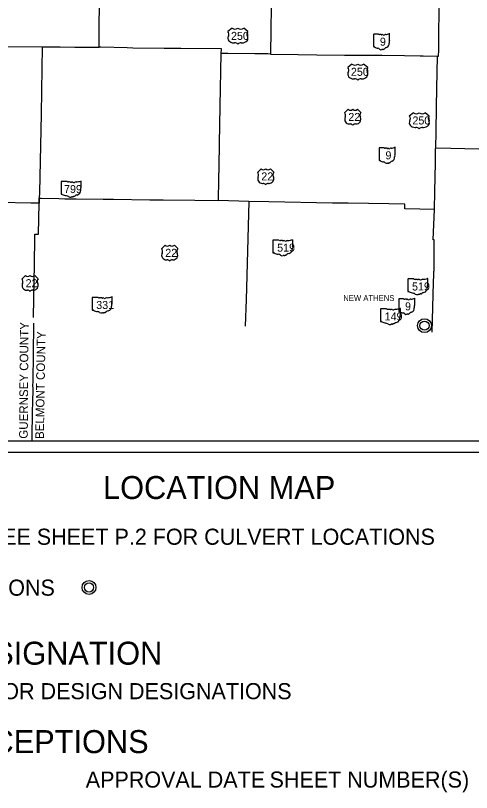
# Model space of a CAD drawing. Extents: x 0 to 34, y -32.5 to 22.
# Drawn here: x 3.67 to 7.63, y 11.04 to 17.8 of the extents above; entities that cross this region are included whole.
import ezdxf

# ---------------------------------------------------------------- set-up
doc = ezdxf.new("R2010")
doc.units = 0
for name, color, linetype in [('GM_X_Adjacent_County', 7, 'Continuous'), ('GM_X_County_Road', 7, 'Continuous'), ('GM_X_County_Road_Text', 7, 'Continuous'), ('GM_X_County_ROW', 7, 'Continuous'), ('GM_X_Minor_Lake_Text', 7, 'Continuous'), ('GM_X_Minor_River', 7, 'Continuous'), ('GM_X_Minor_River_Text', 7, 'Continuous'), ('GM_X_Township', 7, 'Continuous')]:
    doc.layers.add(name, color=color, linetype=linetype)

msp = doc.modelspace()

# ---------------------------------------------------------------- linework, layer by layer
at = {"layer": 'GM_X_Adjacent_County'}
for centre, radius in [((7.2238, 15.1013), 0.06), ((7.2238, 15.1013), 0.04), ((4.3048, 12.8249), 0.06), ((4.3048, 12.8249), 0.04)]:
    msp.add_circle(centre, radius, dxfattribs=at)
at = {"layer": 'GM_X_County_Road_Text'}
msp.add_lwpolyline([(3.8222, 15.1223), (3.819, 14.8503), (3.8155, 14.6249), (3.8154, 14.617), (3.8142, 14.5801), (3.8147, 14.554), (3.8122, 14.4309), (3.8104, 14.3615), (3.8091, 14.3107), (3.8066, 14.1687), (3.8059, 14.1)], dxfattribs=at)
at = {"layer": 'GM_X_County_ROW'}
for points in [[(7.321, 16.6465), (7.3246, 16.7856), (7.3288, 17.0035), (7.3306, 17.1648), (7.3383, 17.4444), (7.3468, 17.4448), (7.3472, 17.4976), (7.3491, 17.6075), (7.3489, 17.6422), (7.3523, 17.8326), (7.3534, 17.8901), (7.3544, 17.9622), (7.3569, 18.1501), (7.3595, 18.2961), (7.3593, 18.3312), (7.3616, 18.5062), (7.3799, 18.5062), (7.6271, 18.5029), (7.8521, 18.4984), (8.053, 18.4945), (8.318, 18.489), (8.6937, 18.4776)], [(5.8906, 17.8717), (5.8866, 17.6728), (5.8829, 17.4634), (5.8599, 17.4636), (5.8264, 17.464), (5.749, 17.4649), (5.5121, 17.4676), (5.4556, 17.4683), (5.4565, 17.5071), (5.1048, 17.5102), (4.9592, 17.5125), (4.6867, 17.5154), (4.6367, 17.5168), (4.4077, 17.5228), (4.393, 17.5229), (4.3934, 17.5648), (4.3922, 17.686), (4.3981, 18.1308)], [(3.0949, 17.5354), (3.2293, 17.5323), (3.8985, 17.5258), (3.8919, 17.1439), (3.8881, 16.941), (3.8731, 16.2596), (3.8722, 16.2095), (3.8718, 16.1665), (3.7972, 16.1673), (3.5262, 16.1718), (3.5138, 16.1719), (3.2094, 16.176), (2.6123, 16.1865), (2.2906, 16.1847), (2.2448, 16.1852)], [(3.8985, 17.5258), (3.9008, 17.5257), (4.0551, 17.525), (4.1816, 17.524), (4.393, 17.5229)], [(7.3099, 16.1125), (7.056, 16.1178), (7.0526, 16.1179), (7.0541, 16.158), (6.9134, 16.1606), (6.5592, 16.1659), (6.4234, 16.1677), (5.8693, 16.1781), (5.6952, 16.1822), (5.4311, 16.189), (5.4351, 16.3752), (5.4369, 16.4875), (5.44, 16.6831), (5.4471, 17.0112), (5.4556, 17.4683)], [(5.8829, 17.4634), (6.1235, 17.4606), (6.2881, 17.4575), (6.5279, 17.4525), (6.8541, 17.4535), (7.0492, 17.4506), (7.1868, 17.4473), (7.2109, 17.4467), (7.3383, 17.4444)], [(7.2893, 15.0436), (7.3033, 15.4758), (7.3037, 15.5438), (7.3048, 15.5766), (7.3083, 15.5766), (7.3085, 15.7229), (7.3089, 15.8468), (7.2997, 15.8466), (7.3099, 16.1125), (7.3135, 16.2676), (7.3192, 16.5173), (7.3208, 16.6424), (7.321, 16.6465), (7.4531, 16.644), (7.8197, 16.6369), (8.1172, 16.6295), (8.1959, 16.6272), (8.2442, 16.6261), (8.3923, 16.6228), (8.6528, 16.6128)], [(3.8226, 15.171), (3.828, 15.5021), (3.8281, 15.5137), (3.8294, 15.6038), (3.8339, 15.8975), (3.8649, 15.897), (3.8718, 16.1665), (3.8722, 16.2095), (3.8872, 16.2094), (4.0414, 16.2069), (4.0954, 16.2051), (4.1927, 16.2039), (4.4267, 16.2022), (4.5177, 16.2007), (4.8334, 16.1961), (4.9511, 16.1945), (5.2258, 16.1916), (5.4311, 16.189)], [(5.6952, 16.1822), (5.6755, 15.4296), (5.6732, 15.3285), (5.6632, 15.0971)]]:
    msp.add_lwpolyline(points, dxfattribs=at)
at = {"layer": 'GM_X_Minor_Lake_Text'}
for p, q in [((5.5495, 17.6879), (5.5132, 17.6589)), ((5.6872, 17.6589), (5.651, 17.6879)), ((5.564, 17.5602), (5.5712, 17.5602)), ((5.6292, 17.5602), (5.6365, 17.5602)), ((6.5927, 17.3755), (6.5565, 17.3465)), ((6.7305, 17.3465), (6.6942, 17.3755)), ((6.6072, 17.2478), (6.6145, 17.2478)), ((6.6725, 17.2478), (6.6797, 17.2478)), ((6.559, 16.9828), (6.53, 16.9538)), ((6.6692, 16.9538), (6.6402, 16.9828)), ((7.128, 16.9524), (7.0917, 16.9234)), ((7.2657, 16.9234), (7.2295, 16.9524)), ((6.5706, 16.8552), (6.5764, 16.8552)), ((6.6228, 16.8552), (6.6286, 16.8552)), ((7.1425, 16.8248), (7.1497, 16.8248)), ((7.2077, 16.8248), (7.215, 16.8248)), ((5.8017, 16.466), (5.7727, 16.437)), ((5.9119, 16.437), (5.8829, 16.466)), ((5.8133, 16.3384), (5.8191, 16.3384)), ((5.8655, 16.3384), (5.8713, 16.3384)), ((4.9662, 15.8012), (4.9372, 15.7722)), ((5.0764, 15.7722), (5.0474, 15.8012)), ((4.9778, 15.6736), (4.9836, 15.6736)), ((5.03, 15.6736), (5.0358, 15.6736)), ((3.7513, 15.5374), (3.7223, 15.5084)), ((3.8615, 15.5084), (3.8325, 15.5374)), ((3.7629, 15.4098), (3.7687, 15.4098)), ((3.8151, 15.4098), (3.8209, 15.4098))]:
    msp.add_line(p, q, dxfattribs=at)
for centre, radius, start, end in [((6.5793, 17.0035), 0.029, 225.573, 314.427), ((6.6199, 17.0035), 0.029, 225.573, 314.427), ((6.5701, 16.8958), 0.0406, 154.83192, 270.63826), ((6.4967, 16.9305), 0.0406, 334.54712, 35.00093), ((6.629, 16.8958), 0.0406, 269.36174, 25.16808), ((6.7024, 16.9305), 0.0406, 144.99907, 205.45288), ((6.5764, 16.8262), 0.029, 36.8699, 90), ((6.6228, 16.8262), 0.029, 90, 143.1301), ((5.7394, 16.4137), 0.0406, 334.54712, 35.00093), ((5.822, 16.4867), 0.029, 225.573, 314.427), ((5.8626, 16.4867), 0.029, 225.573, 314.427), ((5.9452, 16.4137), 0.0406, 144.99907, 205.45288), ((5.8129, 16.379), 0.0406, 154.83192, 270.63826), ((5.8718, 16.379), 0.0406, 269.36174, 25.16808), ((5.8191, 16.3094), 0.029, 36.8699, 90), ((5.8655, 16.3094), 0.029, 90, 143.1301), ((4.9039, 15.7489), 0.0406, 334.54712, 35.00093), ((4.9865, 15.8219), 0.029, 225.573, 314.427), ((5.0271, 15.8219), 0.029, 225.573, 314.427), ((5.1096, 15.7489), 0.0406, 144.99907, 205.45288), ((4.9773, 15.7142), 0.0406, 154.83192, 270.63826), ((5.0362, 15.7142), 0.0406, 269.36174, 25.16808), ((4.9836, 15.6446), 0.029, 36.8699, 90), ((5.03, 15.6446), 0.029, 90, 143.1301), ((3.6891, 15.4851), 0.0406, 334.54712, 35.00093), ((3.7716, 15.5581), 0.029, 225.573, 314.427), ((3.8122, 15.5581), 0.029, 225.573, 314.427), ((3.8948, 15.4851), 0.0406, 144.99907, 205.45288), ((3.7625, 15.4504), 0.0406, 154.83192, 270.63826), ((3.7687, 15.3808), 0.029, 36.8699, 90), ((3.8151, 15.3808), 0.029, 90, 143.1301), ((3.8214, 15.4504), 0.0406, 269.36174, 25.16808)]:
    msp.add_arc(centre, radius, start, end, dxfattribs=at)
for centre, major_axis, start_param, end_param in [((5.4716, 17.6356), (0.0508, 0), 5.838949, 6.894067), ((5.5749, 17.7086), (-0.0363, 0), 0.795399, 2.346194), ((5.6256, 17.7086), (-0.0363, 0), 0.795399, 2.346194), ((5.7288, 17.6356), (-0.0508, 0), 5.672304, 6.727422), ((5.5634, 17.6008), (0.0508, 0), 2.702327, 4.723529), ((5.6371, 17.6008), (-0.0508, 0), 1.559657, 3.580859), ((5.5712, 17.5312), (-0.0363, 0), 3.785094, 4.712389), ((5.6292, 17.5312), (-0.0363, 0), 4.712389, 5.639684), ((6.6181, 17.3962), (-0.0363, 0), 0.795399, 2.346194), ((6.6688, 17.3962), (-0.0363, 0), 0.795399, 2.346194), ((6.6066, 17.2884), (0.0508, 0), 2.702327, 4.723529), ((6.5149, 17.3232), (0.0508, 0), 5.838949, 6.894067), ((6.6803, 17.2884), (-0.0508, 0), 1.559657, 3.580859), ((6.7721, 17.3232), (-0.0508, 0), 5.672304, 6.727422), ((6.6145, 17.2188), (-0.0363, 0), 3.785094, 4.712389), ((6.6725, 17.2188), (-0.0363, 0), 4.712389, 5.639684), ((7.0501, 16.9001), (0.0508, 0), 5.838949, 6.894067), ((7.1534, 16.9731), (-0.0363, 0), 0.795399, 2.346194), ((7.2041, 16.9731), (-0.0363, 0), 0.795399, 2.346194), ((7.3073, 16.9001), (-0.0508, 0), 5.672304, 6.727422), ((7.1419, 16.8654), (0.0508, 0), 2.702327, 4.723529), ((7.1497, 16.7958), (-0.0363, 0), 3.785094, 4.712389), ((7.2077, 16.7958), (-0.0363, 0), 4.712389, 5.639684), ((7.2155, 16.8654), (-0.0508, 0), 1.559657, 3.580859)]:
    msp.add_ellipse(centre, major_axis=major_axis, ratio=0.8, start_param=start_param, end_param=end_param, dxfattribs=at)
at = {"layer": 'GM_X_Minor_River_Text'}
for p, q in [((6.7815, 17.6342), (6.7815, 17.5285)), ((6.8236, 17.636), (6.7829, 17.636)), ((6.9207, 17.5834), (6.9207, 17.6386)), ((6.9207, 17.5834), (6.9207, 17.5834)), ((6.8297, 16.646), (6.8297, 16.5403)), ((6.8718, 16.6478), (6.831, 16.6478)), ((6.9689, 16.5951), (6.9689, 16.6504)), ((6.9689, 16.5951), (6.9689, 16.5951)), ((4.0616, 16.3525), (4.0616, 16.2468)), ((4.1142, 16.3543), (4.0633, 16.3543)), ((4.2356, 16.3016), (4.2356, 16.3569)), ((4.2356, 16.3017), (4.2356, 16.3016)), ((5.9051, 15.8427), (5.9051, 15.7371)), ((5.9578, 15.8446), (5.9069, 15.8446)), ((6.0792, 15.7919), (6.0792, 15.8472)), ((6.0791, 15.7919), (6.0792, 15.7919)), ((7.0786, 15.5053), (7.0786, 15.3996)), ((7.1313, 15.5071), (7.0803, 15.5071)), ((7.2526, 15.4544), (7.2526, 15.5097)), ((7.2526, 15.4544), (7.2526, 15.4544)), ((4.3321, 15.3447), (4.3321, 15.239)), ((4.3848, 15.3465), (4.3339, 15.3465)), ((4.5062, 15.2938), (4.5062, 15.3491)), ((7.1394, 15.2819), (7.1394, 15.3372)), ((4.5062, 15.2938), (4.5062, 15.2938)), ((7.0002, 15.3328), (7.0002, 15.2271)), ((7.0423, 15.3346), (7.0015, 15.3346)), ((7.1394, 15.282), (7.1394, 15.2819)), ((6.8408, 15.2446), (6.8408, 15.1389)), ((6.8935, 15.2464), (6.8425, 15.2464)), ((7.0148, 15.1937), (7.0148, 15.249)), ((7.0148, 15.1937), (7.0148, 15.1937))]:
    msp.add_line(p, q, dxfattribs=at)
for centre, radius, start, end in [((6.7831, 17.6344), 0.00161, 98.1301, 188.1301), ((6.8333, 17.6483), 0.0156, 231.61951, 271.11188), ((6.8385, 17.5767), 0.0562, 80.48669, 94.98827), ((6.8899, 17.6037), 0.0297, 97.34618, 120.76885), ((6.8711, 17.7801), 0.1476, 275.84447, 288.90645), ((6.9192, 17.6389), 0.00155, 351.86209, 97.738), ((6.8513, 17.635), 0.00451, 219.79206, 297.10237), ((6.8579, 17.6228), 0.00938, 54.46668, 119.14113), ((6.87, 17.6395), 0.0113, 233.85621, 294.82819), ((6.9262, 17.5602), 0.0105, 136.8065, 186.92959), ((6.9203, 17.5793), 0.0024, 107.94398, 210.33697), ((6.9051, 17.5723), 0.0144, 340.03296, 23.64957), ((6.919, 17.5831), 0.00166, 289.60381, 7.73413), ((6.7831, 17.5283), 0.00163, 171.95839, 258.30661), ((6.7833, 17.5391), 0.0124, 267.33899, 280.60386), ((6.7859, 17.5224), 0.00448, 29.74838, 93.27175), ((6.8424, 17.6174), 0.1066, 240.41292, 257.1985), ((6.8106, 17.4811), 0.0334, 47.18416, 75.83597), ((6.8467, 17.5219), 0.0212, 230.70037, 286.29184), ((6.8589, 17.4854), 0.0174, 85.69512, 111.20995), ((6.8605, 17.514), 0.0113, 268.77702, 315.54927), ((6.8707, 17.5038), 0.00318, 65.75173, 132.64842), ((6.8693, 17.5183), 0.0119, 282.87319, 323.27711), ((6.8949, 17.4989), 0.0202, 94.40312, 142.57675), ((6.8794, 17.5532), 0.0369, 292.30889, 8.98584), ((6.8313, 16.6462), 0.00161, 98.1301, 188.1301), ((6.8815, 16.66), 0.0156, 231.61951, 271.11188), ((6.8867, 16.5885), 0.0562, 80.48669, 94.98827), ((6.8994, 16.6467), 0.00451, 219.79206, 297.10237), ((6.9061, 16.6345), 0.00938, 54.46668, 119.14113), ((6.9182, 16.6513), 0.0113, 233.85621, 294.82819), ((6.9381, 16.6155), 0.0297, 97.34618, 120.76885), ((6.9193, 16.7918), 0.1476, 275.84447, 288.90645), ((6.9673, 16.6506), 0.00155, 351.86209, 97.738), ((6.9276, 16.565), 0.0369, 292.30889, 8.98584), ((6.9744, 16.572), 0.0105, 136.8065, 186.92959), ((6.9685, 16.5911), 0.0024, 107.94398, 210.33697), ((6.9533, 16.5841), 0.0144, 340.03296, 23.64957), ((6.9672, 16.5949), 0.00166, 289.60381, 7.73413), ((6.8313, 16.5401), 0.00163, 171.95839, 258.30661), ((6.8315, 16.5509), 0.0124, 267.33899, 280.60386), ((6.8341, 16.5342), 0.00448, 29.74838, 93.27175), ((6.8906, 16.6291), 0.1066, 240.41292, 257.1985), ((6.8588, 16.4928), 0.0334, 47.18416, 75.83597), ((6.8949, 16.5337), 0.0212, 230.70037, 286.29184), ((6.9071, 16.4971), 0.0174, 85.69512, 111.20995), ((6.9087, 16.5258), 0.0113, 268.77702, 315.54927), ((6.9189, 16.5155), 0.00318, 65.75173, 132.64842), ((6.9175, 16.5301), 0.0119, 282.87319, 323.27711), ((6.9431, 16.5106), 0.0202, 94.40312, 142.57675), ((7.0898, 15.4787), 0.1476, 275.84447, 288.90645), ((7.1378, 15.3374), 0.00155, 351.86209, 97.738), ((7.0018, 15.333), 0.00161, 98.1301, 188.1301), ((7.052, 15.3469), 0.0156, 231.61951, 271.11188), ((7.0572, 15.2753), 0.0562, 80.48669, 94.98827), ((7.0699, 15.3336), 0.00451, 219.79206, 297.10237), ((7.0766, 15.3213), 0.00938, 54.46668, 119.14113), ((7.0887, 15.3381), 0.0113, 233.85621, 294.82819), ((7.1086, 15.3023), 0.0297, 97.34618, 120.76885), ((7.139, 15.2779), 0.0024, 107.94398, 210.33697), ((7.1238, 15.2709), 0.0144, 340.03296, 23.64957), ((7.1377, 15.2817), 0.00166, 289.60381, 7.73413), ((7.0018, 15.2269), 0.00163, 171.95839, 258.30661), ((7.002, 15.2377), 0.0124, 267.33899, 280.60386), ((7.0046, 15.221), 0.00448, 29.74838, 93.27175), ((7.0611, 15.316), 0.1066, 240.41292, 257.1985), ((7.0293, 15.1797), 0.0334, 47.18416, 75.83597), ((7.0654, 15.2205), 0.0212, 230.70037, 286.29184), ((7.0776, 15.184), 0.0174, 85.69512, 111.20995), ((7.0792, 15.2126), 0.0113, 268.77702, 315.54927), ((7.0894, 15.2024), 0.00318, 65.75173, 132.64842), ((7.088, 15.2169), 0.0119, 282.87319, 323.27711), ((7.1136, 15.1975), 0.0202, 94.40312, 142.57675), ((7.0981, 15.2518), 0.0369, 292.30889, 8.98584), ((7.1449, 15.2588), 0.0105, 136.8065, 186.92959)]:
    msp.add_arc(centre, radius, start, end, dxfattribs=at)
for centre, major_axis, start_param, end_param in [((4.0635, 16.3527), (0.00202, 0), 1.712693, 3.28349), ((4.1264, 16.3666), (0.0196, 0), 4.042523, 4.731795), ((4.1328, 16.295), (0.0702, 0), 1.404758, 1.657858), ((4.1488, 16.3533), (0.00564, 0), 3.836095, 5.185415), ((4.1571, 16.341), (0.0117, 0), 0.950623, 2.079405), ((4.1971, 16.322), (0.0371, 0), 1.699011, 2.107814), ((4.1736, 16.4984), (0.1845, 0), 4.814394, 5.042369), ((4.2336, 16.3571), (0.00194, 0), 6.141152, 7.989035), ((4.1722, 16.3578), (0.0141, 0), 4.081561, 5.145723), ((4.2425, 16.2785), (0.0131, 0), 2.387724, 3.262537), ((4.2351, 16.2976), (0.003, 0), 1.883978, 3.671073), ((4.216, 16.2906), (0.018, 0), 5.934695, 6.695948), ((4.2335, 16.3014), (0.00207, 0), 5.05454, 6.418171), ((4.0636, 16.2466), (0.00203, 0), 3.00124, 4.508301), ((4.0639, 16.2574), (0.0155, 0), 4.665946, 4.897461), ((4.067, 16.2407), (0.0056, 0), 0.519207, 1.627899), ((4.1377, 16.3357), (0.1333, 0), 4.195997, 4.488961), ((4.098, 16.1993), (0.0417, 0), 0.823519, 1.323587), ((4.1431, 16.2402), (0.0265, 0), 4.026481, 4.996735), ((4.1584, 16.2037), (0.0217, 0), 1.495662, 1.94098), ((4.1603, 16.2323), (0.0141, 0), 4.691044, 5.507374), ((4.173, 16.2221), (0.00397, 0), 1.147584, 2.315152), ((4.1714, 16.2366), (0.0149, 0), 4.937069, 5.64225), ((4.2034, 16.2172), (0.0253, 0), 1.647645, 2.488434), ((4.1839, 16.2715), (0.0462, 0), 5.101752, 6.440018), ((5.9071, 15.843), (0.00202, 0), 1.712693, 3.28349), ((5.97, 15.8568), (0.0196, 0), 4.042523, 4.731795), ((5.9764, 15.7852), (0.0702, 0), 1.404758, 1.657858), ((5.9924, 15.8435), (0.00564, 0), 3.836095, 5.185415), ((6.0007, 15.8313), (0.0117, 0), 0.950623, 2.079405), ((6.0158, 15.8481), (0.0141, 0), 4.081561, 5.145723), ((6.0407, 15.8123), (0.0371, 0), 1.699011, 2.107814), ((6.0172, 15.9886), (0.1845, 0), 4.814394, 5.042369), ((6.0772, 15.8474), (0.00194, 0), 6.141152, 7.989035), ((6.0275, 15.7617), (0.0462, 0), 5.101752, 6.440018), ((6.0861, 15.7688), (0.0131, 0), 2.387724, 3.262537), ((6.0787, 15.7878), (0.003, 0), 1.883978, 3.671073), ((6.0596, 15.7809), (0.018, 0), 5.934695, 6.695948), ((6.0771, 15.7917), (0.00207, 0), 5.05454, 6.418171), ((5.9072, 15.7368), (0.00203, 0), 3.00124, 4.508301), ((5.9075, 15.7477), (0.0155, 0), 4.665946, 4.897461), ((5.9106, 15.731), (0.0056, 0), 0.519207, 1.627899), ((5.9813, 15.8259), (0.1333, 0), 4.195997, 4.488961), ((5.9416, 15.6896), (0.0417, 0), 0.823519, 1.323587), ((5.9867, 15.7305), (0.0265, 0), 4.026481, 4.996735), ((6.002, 15.6939), (0.0217, 0), 1.495662, 1.94098), ((6.0039, 15.7225), (0.0141, 0), 4.691044, 5.507374), ((6.0166, 15.7123), (0.00397, 0), 1.147584, 2.315152), ((6.0149, 15.7268), (0.0149, 0), 4.937069, 5.64225), ((6.047, 15.7074), (0.0253, 0), 1.647645, 2.488434), ((7.0806, 15.5055), (0.00202, 0), 1.712693, 3.28349), ((7.1434, 15.5193), (0.0196, 0), 4.042523, 4.731795), ((7.1499, 15.4478), (0.0702, 0), 1.404758, 1.657858), ((7.1659, 15.506), (0.00564, 0), 3.836095, 5.185415), ((7.1741, 15.4938), (0.0117, 0), 0.950623, 2.079405), ((7.1893, 15.5106), (0.0141, 0), 4.081561, 5.145723), ((7.2142, 15.4748), (0.0371, 0), 1.699011, 2.107814), ((7.1907, 15.6511), (0.1845, 0), 4.814394, 5.042369), ((7.2507, 15.5099), (0.00194, 0), 6.141152, 7.989035), ((7.201, 15.4243), (0.0462, 0), 5.101752, 6.440018), ((7.2596, 15.4313), (0.0131, 0), 2.387724, 3.262537), ((7.2522, 15.4504), (0.003, 0), 1.883978, 3.671073), ((7.2331, 15.4434), (0.018, 0), 5.934695, 6.695948), ((7.2506, 15.4542), (0.00207, 0), 5.05454, 6.418171), ((4.3341, 15.3449), (0.00202, 0), 1.712693, 3.28349), ((4.397, 15.3587), (0.0196, 0), 4.042523, 4.731795), ((4.4034, 15.2872), (0.0702, 0), 1.404758, 1.657858), ((4.4194, 15.3454), (0.00564, 0), 3.836095, 5.185415), ((4.4277, 15.3332), (0.0117, 0), 0.950623, 2.079405), ((4.4428, 15.35), (0.0141, 0), 4.081561, 5.145723), ((4.4677, 15.3142), (0.0371, 0), 1.699011, 2.107814), ((4.4442, 15.4905), (0.1845, 0), 4.814394, 5.042369), ((4.5042, 15.3493), (0.00194, 0), 6.141152, 7.989035), ((7.0806, 15.3994), (0.00203, 0), 3.00124, 4.508301), ((7.0809, 15.4102), (0.0155, 0), 4.665946, 4.897461), ((7.0841, 15.3935), (0.0056, 0), 0.519207, 1.627899), ((7.1548, 15.4884), (0.1333, 0), 4.195997, 4.488961), ((7.115, 15.3521), (0.0417, 0), 0.823519, 1.323587), ((7.1601, 15.393), (0.0265, 0), 4.026481, 4.996735), ((7.1754, 15.3564), (0.0217, 0), 1.495662, 1.94098), ((7.1774, 15.3851), (0.0141, 0), 4.691044, 5.507374), ((7.1901, 15.3748), (0.00397, 0), 1.147584, 2.315152), ((7.1884, 15.3894), (0.0149, 0), 4.937069, 5.64225), ((7.2205, 15.3699), (0.0253, 0), 1.647645, 2.488434), ((4.4545, 15.2637), (0.0462, 0), 5.101752, 6.440018), ((4.5131, 15.2707), (0.0131, 0), 2.387724, 3.262537), ((4.5057, 15.2898), (0.003, 0), 1.883978, 3.671073), ((4.4866, 15.2828), (0.018, 0), 5.934695, 6.695948), ((4.5041, 15.2936), (0.00207, 0), 5.05454, 6.418171), ((4.3342, 15.2388), (0.00203, 0), 3.00124, 4.508301), ((4.3345, 15.2496), (0.0155, 0), 4.665946, 4.897461), ((4.3376, 15.2329), (0.0056, 0), 0.519207, 1.627899), ((4.4083, 15.3278), (0.1333, 0), 4.195997, 4.488961), ((4.3686, 15.1915), (0.0417, 0), 0.823519, 1.323587), ((4.4137, 15.2324), (0.0265, 0), 4.026481, 4.996735), ((4.429, 15.1958), (0.0217, 0), 1.495662, 1.94098), ((4.4309, 15.2245), (0.0141, 0), 4.691044, 5.507374), ((4.4436, 15.2142), (0.00397, 0), 1.147584, 2.315152), ((4.442, 15.2288), (0.0149, 0), 4.937069, 5.64225), ((4.474, 15.2093), (0.0253, 0), 1.647645, 2.488434), ((6.8428, 15.2448), (0.00202, 0), 1.712693, 3.28349), ((6.9056, 15.2586), (0.0196, 0), 4.042523, 4.731795), ((6.9121, 15.1871), (0.0702, 0), 1.404758, 1.657858), ((6.928, 15.2453), (0.00564, 0), 3.836095, 5.185415), ((6.9363, 15.2331), (0.0117, 0), 0.950623, 2.079405), ((6.9515, 15.2499), (0.0141, 0), 4.081561, 5.145723), ((6.9764, 15.2141), (0.0371, 0), 1.699011, 2.107814), ((6.9528, 15.3904), (0.1845, 0), 4.814394, 5.042369), ((7.0129, 15.2492), (0.00194, 0), 6.141152, 7.989035), ((6.8428, 15.1387), (0.00203, 0), 3.00124, 4.508301), ((6.8431, 15.1495), (0.0155, 0), 4.665946, 4.897461), ((6.8463, 15.1328), (0.0056, 0), 0.519207, 1.627899), ((6.917, 15.2277), (0.1333, 0), 4.195997, 4.488961), ((6.9632, 15.1636), (0.0462, 0), 5.101752, 6.440018), ((7.0218, 15.1706), (0.0131, 0), 2.387724, 3.262537), ((7.0144, 15.1897), (0.003, 0), 1.883978, 3.671073), ((6.9953, 15.1827), (0.018, 0), 5.934695, 6.695948), ((7.0128, 15.1935), (0.00207, 0), 5.05454, 6.418171), ((6.8772, 15.0914), (0.0417, 0), 0.823519, 1.323587), ((6.9223, 15.1323), (0.0265, 0), 4.026481, 4.996735), ((6.9376, 15.0957), (0.0217, 0), 1.495662, 1.94098), ((6.9395, 15.1244), (0.0141, 0), 4.691044, 5.507374), ((6.9523, 15.1141), (0.00397, 0), 1.147584, 2.315152), ((6.9506, 15.1287), (0.0149, 0), 4.937069, 5.64225), ((6.9826, 15.1092), (0.0253, 0), 1.647645, 2.488434)]:
    msp.add_ellipse(centre, major_axis=major_axis, ratio=0.8, start_param=start_param, end_param=end_param, dxfattribs=at)
at = {"layer": 'GM_X_Township'}
for p, q in [((2.1, 14.1), (8.9, 14.1)), ((2, 14), (9, 14))]:
    msp.add_line(p, q, dxfattribs=at)

# ---------------------------------------------------------------- texts
at = {"layer": 'GM_X_Adjacent_County'}
for s, height, p in [('LOCATION MAP', 0.2, (4.4269, 13.5938)), ('SEE SHEET P.2 FOR CULVERT LOCATIONS', 0.14, (3.4239, 13.1959)), ('PROJECT LOCATIONS', 0.14, (2, 12.7531)), ('APPROVAL DATE', 0.14, (4.2763, 11.0843)), ('SHEET NUMBER(S)', 0.14, (5.8755, 11.0843))]:
    msp.add_text(s, height=height, dxfattribs=at).set_placement(p)
at = {"layer": 'GM_X_County_Road'}
msp.add_text('NEW ATHENS', height=0.05, rotation=0.00001, dxfattribs=at).set_placement((6.5168, 15.3167))
at = {"layer": 'GM_X_Minor_Lake_Text'}
for s, p in [('250', (5.5404, 17.5863)), ('250', (6.5836, 17.2739)), ('22', (6.561, 16.8813)), ('250', (7.1189, 16.8509)), ('22', (5.8038, 16.3645)), ('22', (4.9682, 15.6997)), ('22', (3.7534, 15.4359))]:
    msp.add_text(s, height=0.06961, dxfattribs=at).set_placement(p)
at = {"layer": 'GM_X_Minor_River'}
for s, rotation, p in [('GUERNSEY COUNTY', 89.56996, (3.7713, 14.1179)), ('BELMONT COUNTY', 89.09129, (3.9119, 14.1155))]:
    msp.add_text(s, height=0.075, rotation=rotation, dxfattribs=at).set_placement(p)
at = {"layer": 'GM_X_Minor_River_Text'}
for s, height, p in [('9', 0.0696, (6.8359, 17.536)), ('9', 0.0696, (6.884, 16.5477)), ('799', 0.06961, (4.0877, 16.2543)), ('519', 0.06961, (5.9418, 15.7445)), ('519', 0.06961, (7.1153, 15.4071)), ('331', 0.06961, (4.3677, 15.2465)), ('9', 0.0696, (7.0545, 15.2346)), ('149', 0.06961, (6.8773, 15.1464))]:
    msp.add_text(s, height=height, dxfattribs=at).set_placement(p)
at = {"layer": 'GM_X_Township'}
for s, height, p in [('DESIGN DESIGNATION', 0.2, (2, 12.1531)), ('SEE SHEET P.2 FOR DESIGN DESIGNATIONS', 0.14, (2, 11.8531)), ('DESIGN EXCEPTIONS', 0.2, (2, 11.3843))]:
    msp.add_text(s, height=height, dxfattribs=at).set_placement(p)

doc.saveas('drawing.dxf')
